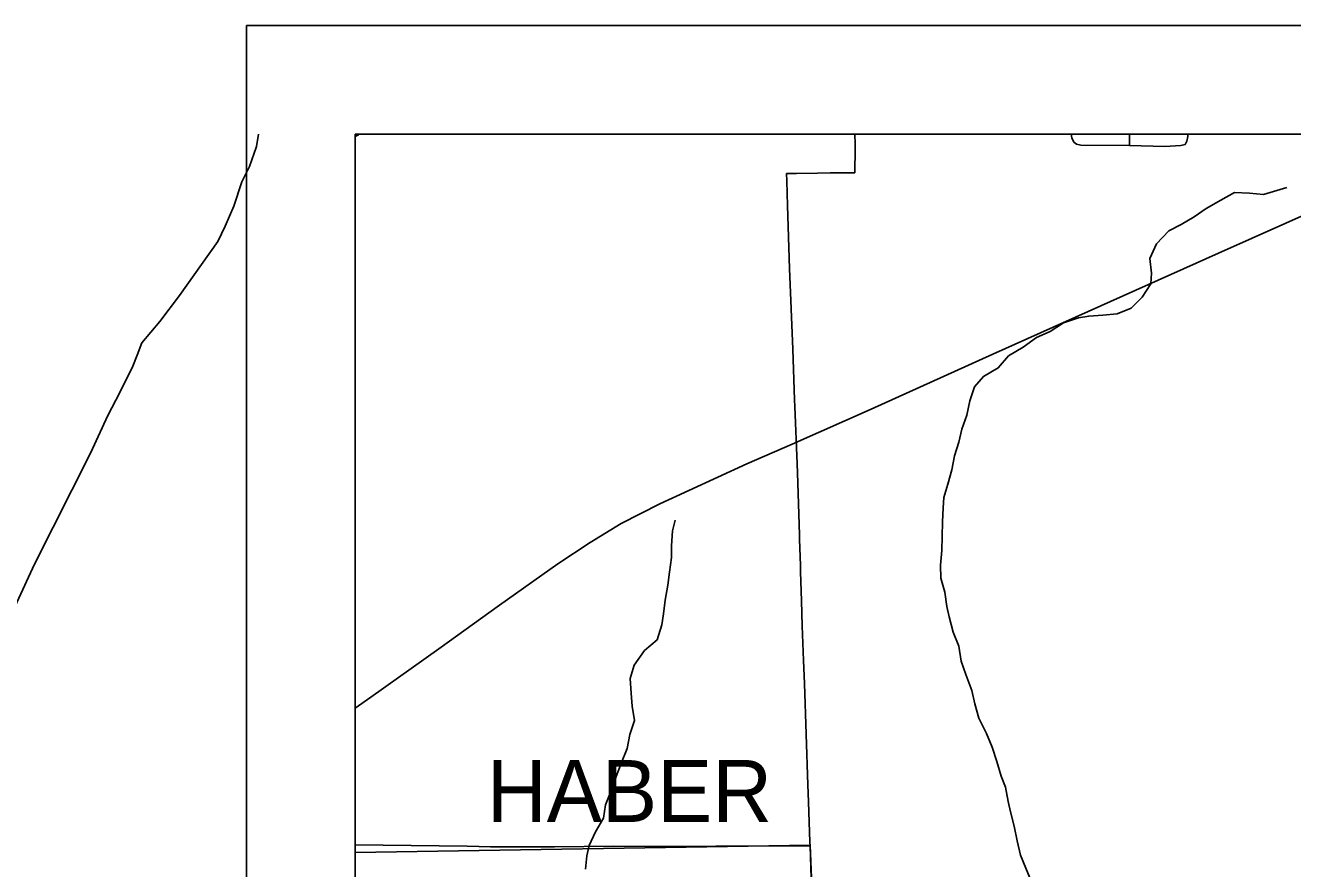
# Model space of a CAD drawing. Extents: x 0 to 34, y 0 to 22.
# Drawn here: x 7.011 to 8.174, y 9.791 to 10.565 of the extents above; entities that cross this region are included whole.
import ezdxf

# ---------------------------------------------------------------- set-up
doc = ezdxf.new("R2010")
doc.units = 0
for name, color, linetype in [('GM_X_City_Street', 7, 'Continuous'), ('GM_X_Corporation', 7, 'Continuous'), ('GM_X_Minor_River', 7, 'Continuous'), ('GM_X_Rail_Line', 7, 'Continuous'), ('GM_X_State_Route', 7, 'Continuous'), ('GM_X_Township_Road', 7, 'Continuous'), ('GM_X_Township_Road_Text', 7, 'Continuous'), ('SH_Cut_Line', 7, 'Continuous'), ('SH_Data', 7, 'Continuous')]:
    doc.layers.add(name, color=color, linetype=linetype)

msp = doc.modelspace()

# ---------------------------------------------------------------- linework, layer by layer
at = {"layer": 'GM_X_City_Street'}
msp.add_line((8.0244, 10.4544), (8.0243, 10.4647), dxfattribs=at)
for points in [[(6.9882, 10.0038), (7.0189, 10.0702), (7.0705, 10.172), (7.0862, 10.2066), (7.0973, 10.2278), (7.1093, 10.2518), (7.1133, 10.2619), (7.1174, 10.2732), (7.1339, 10.2929), (7.1521, 10.3167), (7.1723, 10.3452), (7.1873, 10.3664), (7.1939, 10.3804), (7.202, 10.3988), (7.2094, 10.421), (7.2163, 10.4352), (7.2229, 10.4534), (7.2245, 10.4647)], [(7.9733, 10.4576), (7.9713, 10.4615), (7.9708, 10.4647)], [(8.0756, 10.4554), (8.077, 10.4583), (8.0778, 10.4627), (8.0778, 10.4647)], [(7.9733, 10.4576), (7.9758, 10.4556), (7.9797, 10.4546), (8.0244, 10.4544), (8.0569, 10.4536), (8.0714, 10.4544), (8.0756, 10.4554)]]:
    msp.add_lwpolyline(points, dxfattribs=at)
at = {"layer": 'GM_X_Corporation'}
msp.add_lwpolyline([(11.9896, 10.4647), (7.3135, 10.4647), (7.3135, 9.8056), (7.731, 9.8121), (7.7328, 9.7749), (7.7363, 9.6619), (8.0484, 9.6696), (8.0537, 9.4909), (8.1999, 9.4907)], dxfattribs=at)
at = {"layer": 'GM_X_Minor_River'}
for points in [[(8.1687, 10.416), (8.1473, 10.4096), (8.1344, 10.4106), (8.1207, 10.4113), (8.1082, 10.4043), (8.0946, 10.3966), (8.0836, 10.3888), (8.0719, 10.3819), (8.0605, 10.3761), (8.0492, 10.3642), (8.0429, 10.3508), (8.0445, 10.3371), (8.0438, 10.3276), (8.0359, 10.3153), (8.0258, 10.305), (8.0129, 10.2999), (8, 10.2987), (7.987, 10.2978), (7.9776, 10.2962), (7.9639, 10.2915), (7.9514, 10.2837), (7.9389, 10.2783), (7.9268, 10.2694), (7.9132, 10.2613), (7.9038, 10.2502), (7.8902, 10.2425), (7.8819, 10.2329), (7.8778, 10.2199), (7.8749, 10.2069), (7.8704, 10.194), (7.8675, 10.1821), (7.8638, 10.1695), (7.8612, 10.1566), (7.8575, 10.1436), (7.8538, 10.1314), (7.8532, 10.1219), (7.8525, 10.1089), (7.8522, 10.0956), (7.852, 10.0827), (7.8509, 10.0693), (7.851, 10.0572), (7.8549, 10.0443), (7.8566, 10.0313), (7.8589, 10.0219), (7.8625, 10.0078), (7.8675, 9.9949), (7.8699, 9.9812), (7.8742, 9.9687), (7.8796, 9.9543), (7.8824, 9.9418), (7.8859, 9.9289), (7.8929, 9.9148), (7.8983, 9.902), (7.9026, 9.8891), (7.9065, 9.8754), (7.9104, 9.8655), (7.9128, 9.8522), (7.9151, 9.8427), (7.9183, 9.8295), (7.9211, 9.8162), (7.9242, 9.8029), (7.9292, 9.7911), (7.9343, 9.7786)], [(7.6073, 10.1105), (7.6047, 10.1006), (7.6037, 10.0869), (7.6038, 10.0762), (7.602, 10.0629), (7.6006, 10.0507), (7.598, 10.037), (7.5966, 10.0244), (7.5948, 10.0145), (7.5907, 10.0008), (7.579, 9.9908), (7.5696, 9.9773), (7.5659, 9.9651), (7.5668, 9.9518), (7.5677, 9.9397), (7.5697, 9.9267), (7.5656, 9.9138), (7.5631, 9.9008), (7.5578, 9.8882), (7.553, 9.8752), (7.5482, 9.8615), (7.5433, 9.8492), (7.5415, 9.8371), (7.534, 9.8244), (7.5281, 9.8118), (7.5262, 9.8023), (7.5248, 9.7901)]]:
    msp.add_lwpolyline(points, dxfattribs=at)
at = {"layer": 'GM_X_Rail_Line'}
for points in [[(7.3135, 10.4627), (7.3163, 10.4643), (7.317, 10.4647)], [(7.3135, 9.9378), (7.3278, 9.9481), (7.3903, 9.9925), (7.4459, 10.0324), (7.4994, 10.0703), (7.529, 10.0901), (7.5576, 10.1076), (7.5931, 10.1256), (7.6729, 10.1622), (7.7147, 10.1803), (7.7872, 10.2124), (7.8988, 10.263), (8.1061, 10.3556), (8.3198, 10.4507), (8.3512, 10.4647)], [(8.7721, 6.4561), (8.7457, 7.068), (8.7378, 7.3393), (8.7039, 8.518), (8.6819, 9.2469), (8.6815, 9.2629), (8.6724, 9.5947), (8.6653, 9.8694), (8.6645, 9.9038), (8.6629, 9.9259), (8.654, 10.1241), (8.6546, 10.1651), (8.6524, 10.193), (8.6512, 10.2283), (8.6484, 10.3111), (8.6461, 10.3762), (8.644, 10.4094), (8.6408, 10.4647), (7.3135, 10.4647), (7.3135, 6.1554)]]:
    msp.add_lwpolyline(points, dxfattribs=at)
at = {"layer": 'GM_X_State_Route'}
msp.add_line((7.7722, 10.4293), (7.7724, 10.4518), dxfattribs=at)
for points in [[(7.7724, 10.4518), (7.7724, 10.4558), (7.7721, 10.4647)], [(7.7094, 10.4286), (7.7185, 10.4288), (7.7379, 10.4291)], [(7.7104, 10.3994), (7.7101, 10.4104), (7.7097, 10.4219), (7.7094, 10.4286)], [(7.7379, 10.4291), (7.7496, 10.4293), (7.766, 10.4292), (7.7722, 10.4293)], [(7.7194, 10.1541), (7.7191, 10.1621), (7.7171, 10.2147), (7.7168, 10.2209), (7.7151, 10.2674), (7.7123, 10.3415), (7.7104, 10.3994)], [(7.731, 9.8115), (7.7309, 9.8149), (7.7297, 9.8521), (7.7291, 9.8677), (7.7259, 9.9607), (7.7251, 9.9816), (7.7239, 10.0135), (7.7231, 10.0365), (7.7222, 10.0631), (7.7223, 10.0693), (7.7214, 10.0927), (7.7213, 10.0971), (7.7194, 10.1541)], [(7.7366, 9.666), (7.735, 9.7075), (7.7326, 9.7685), (7.7325, 9.7722), (7.731, 9.8115)]]:
    msp.add_lwpolyline(points, dxfattribs=at)
at = {"layer": 'GM_X_Township_Road'}
msp.add_lwpolyline([(7.3135, 9.8126), (7.4162, 9.8114), (7.4375, 9.8108), (7.4963, 9.8105), (7.5507, 9.8112), (7.6075, 9.8111), (7.6446, 9.8114), (7.7055, 9.8117), (7.7239, 9.8116), (7.731, 9.8115)], dxfattribs=at)
at = {"layer": 'SH_Cut_Line'}
msp.add_lwpolyline([(8.7721, 6.4561), (8.7457, 7.068), (8.7378, 7.3393), (8.7039, 8.518), (8.6819, 9.2469), (8.6815, 9.2629), (8.6724, 9.5947), (8.6653, 9.8694), (8.6645, 9.9038), (8.6629, 9.9259), (8.654, 10.1241), (8.6546, 10.1651), (8.6524, 10.193), (8.6512, 10.2283), (8.6484, 10.3111), (8.6461, 10.3762), (8.644, 10.4094), (8.6408, 10.4647), (7.3135, 10.4647), (7.3135, 3.6647)], dxfattribs=at)
at = {"layer": 'SH_Data'}
for p, q in [((7.2135, 10.5647), (14.2135, 10.5647)), ((7.2135, 10.5647), (7.2135, 3.5647)), ((7.3135, 10.4647), (7.3135, 3.6647)), ((7.3135, 10.4647), (14.1135, 10.4647))]:
    msp.add_line(p, q, dxfattribs=at)

# ---------------------------------------------------------------- texts
at = {"layer": 'GM_X_Township_Road_Text'}
msp.add_text('HABER', height=0.05682, rotation=359.9962, dxfattribs=at).set_placement((7.4344, 9.8335))

doc.saveas('drawing.dxf')
